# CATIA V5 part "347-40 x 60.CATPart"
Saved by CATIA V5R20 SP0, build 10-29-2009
Part number: 347-40 x 60
Definition: NONE
Nomenclature: 347-40 x 60
Source: Unknown
Description: 347-40 x 60
Bounding box of the stored display mesh (mm): x 0 to 60, y -27.5 to 27.5, z -27.5 to 27.5
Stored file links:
  C:\Users\Utente\Desktop\IO LAVORO\3D X SITO CF\X SITO\3D files 347\347-40 x 60.CATPart
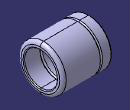
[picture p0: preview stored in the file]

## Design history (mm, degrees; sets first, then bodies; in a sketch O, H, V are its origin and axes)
Body1 "347-40 x 60" (main body)
  Solid1: solid without history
